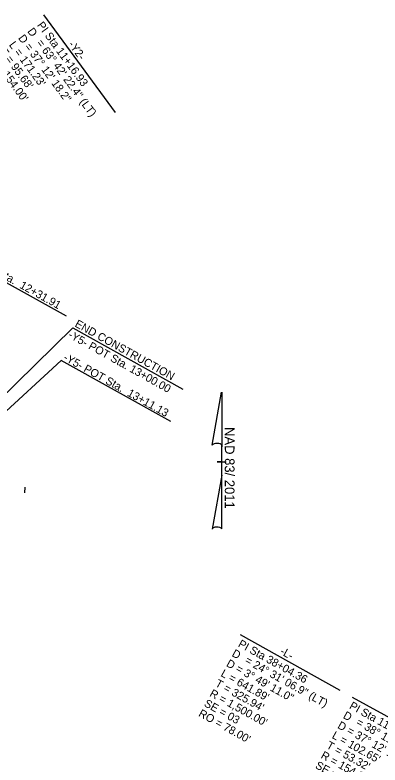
# Model space of a CAD drawing. Extents: x 1762196 to 1766326, y 709922 to 713142.
# Drawn here: x 1764411 to 1764730, y 711303 to 711959 of the extents above; entities that cross this region are included whole.
import ezdxf

# ---------------------------------------------------------------- set-up
doc = ezdxf.new("R2010")
doc.units = 0
for name, color, linetype in [('Pattern 1', 7, 'Continuous'), ('Pattern 2', 7, 'Continuous'), ('Prop Conc 2ft 6in Curb and Gutter', 7, 'Continuous'), ('Prop Dimension', 7, 'Continuous'), ('Prop EOT', 7, 'Continuous'), ('Prop Horizontal Alignment', 7, 'Continuous'), ('Prop Horizontal Alignment Curve and Spiral Data', 7, 'Continuous'), ('Prop Horizontal Alignment Station Label', 7, 'Continuous'), ('Prop Horizontal Alignment Tick Small', 7, 'Continuous'), ('Prop North Arrow NAD83 for Plan Sheets CELL', 7, 'Continuous')]:
    doc.layers.add(name, color=color, linetype=linetype)

msp = doc.modelspace()

# ---------------------------------------------------------------- linework, layer by layer
at = {"layer": 'Pattern 1'}
for radius in [1473.5, 1468.5]:
    msp.add_arc((1765296.46, 712280.56), radius, 220.01407, 240.8436, dxfattribs=at)
at = {"layer": 'Pattern 2'}
for radius in [1473.5, 1468.5]:
    msp.add_arc((1765296.46, 712280.56), radius, 220.01407, 240.8436, dxfattribs=at)
at = {"layer": 'Prop Conc 2ft 6in Curb and Gutter'}
msp.add_arc((1765296.46, 712280.56), 1478, 220.01407, 240.8436, dxfattribs=at)
at = {"layer": 'Prop Dimension'}
msp.add_arc((1765296.46, 712280.56), 1392.37, 222.11492, 230.90027, dxfattribs=at)
at = {"layer": 'Prop EOT'}
msp.add_arc((1765296.46, 712280.56), 1480, 220.01407, 240.8436, dxfattribs=at)
at = {"layer": 'Prop Horizontal Alignment'}
msp.add_arc((1765296.46, 712280.56), 1500, 216.32502, 240.8436, dxfattribs=at)
at = {"layer": 'Prop Horizontal Alignment Curve and Spiral Data'}
for p, q in [((1764435.5, 711959.06), (1764498.19, 711873.75)), ((1764607.52, 711417.28), (1764694.96, 711368.59)), ((1764705.67, 711362.62), (1764793.89, 711313.5))]:
    msp.add_line(p, q, dxfattribs=at)
at = {"layer": 'Prop Horizontal Alignment Station Label'}
for p, q in [((1764455.78, 711695.57), (1764364.45, 711746.43)), ((1764461.21, 711685.37), (1764319.42, 711546.5)), ((1764461.21, 711685.37), (1764557.4, 711631.8)), ((1764330.54, 711546.13), (1764451.2, 711656.86)), ((1764546.93, 711603.56), (1764451.2, 711656.86))]:
    msp.add_line(p, q, dxfattribs=at)
at = {"layer": 'Prop Horizontal Alignment Tick Small'}
msp.add_line((1764419.27, 711541.25), (1764419.57, 711546.25), dxfattribs=at)
at = {"layer": 'Prop North Arrow NAD83 for Plan Sheets CELL'}
for p, q in [((1764583.24, 711582.99), (1764591.44, 711629.34)), ((1764591.49, 711629.34), (1764591.49, 711581.54)), ((1764591.49, 711556.74), (1764591.49, 711582.94)), ((1764591.49, 711581.54), (1764591.49, 711582.89)), ((1764587.49, 711568.34), (1764587.44, 711568.34)), ((1764591.04, 711568.34), (1764587.49, 711568.34)), ((1764587.54, 711568.34), (1764595.54, 711568.34)), ((1764591.49, 711556.74), (1764583.14, 711509.49)), ((1764591.54, 711509.69), (1764591.49, 711556.74))]:
    msp.add_line(p, q, dxfattribs=at)
for centre, start_param, end_param in [((1764587.38, 711582.5), 0.216388, 2.908219), ((1764587.38, 711509.33), 0.201328, 3.141593)]:
    msp.add_ellipse(centre, major_axis=(4.23, -0.03), ratio=0.461098, start_param=start_param, end_param=end_param, dxfattribs=at)

# ---------------------------------------------------------------- texts
at = {"layer": 'Prop Horizontal Alignment Curve and Spiral Data'}
for s, rotation, p in [('PI Sta 11+16.93', 306.31306, (1764429.67, 711950.1)), ('D', 306.31306, (1764421.21, 711944.72)), ('D = 37%%d 12\' 18.2"', 306.31306, (1764413.15, 711938.8)), ("L = 171.23'", 306.31306, (1764405.09, 711932.88)), ('= 63%%d 42\' 22.4" (LT)', 306.31306, (1764429.06, 711934.54)), ('-Y2-', 306.31306, (1764456.9, 711933.27)), ("T = 95.68'", 306.31306, (1764397.04, 711926.96)), ("R = 154.00'", 306.31306, (1764388.98, 711921.03)), ('PI Sta 38+04.36', 330.88754, (1764605.24, 711407.11)), ('D', 330.88754, (1764599.78, 711398.7)), ('-L-', 330.88754, (1764641.88, 711400.65)), ('D = 3%%d 49\' 11.0"', 330.88754, (1764594.92, 711389.96)), ('= 24%%d 31\' 06.9" (LT)', 330.88754, (1764611.15, 711392.71)), ("L = 641.89'", 330.88754, (1764590.05, 711381.23)), ("T = 325.94'", 330.88754, (1764585.19, 711372.49)), ("R = 1,500.00'", 330.88754, (1764580.32, 711363.75)), ('SE = 03', 330.88754, (1764575.46, 711355.02)), ('PI Sta 11+82.58', 330.88754, (1764702.5, 711352.94)), ("RO = 78.00'", 330.88754, (1764570.59, 711346.28)), ('D', 330.88754, (1764697.05, 711344.53)), ('D = 37%%d 12\' 18.2"', 330.88754, (1764692.19, 711335.8)), ('= 38%%d 11\' 33.2" (RT)', 330.88754, (1764708.42, 711338.54)), ("L = 102.65'", 330.88754, (1764687.32, 711327.06)), ("T = 53.32'", 330.88754, (1764682.45, 711318.32)), ("R = 154.00'", 330.88754, (1764677.59, 711309.59)), ('SE = 02', 330.88754, (1764672.72, 711300.85))]:
    msp.add_text(s, height=7, rotation=rotation, dxfattribs=at).set_placement(p)
at = {"layer": 'Prop Horizontal Alignment Station Label'}
for s, p in [('-Y5- PT Sta.  12+31.91', (1764364.67, 711748.32)), ('END CONSTRUCTION', (1764462.41, 711686.91)), ('-Y5- POT Sta. 13+00.00', (1764456.58, 711677.41)), ('-Y5- POT Sta.  13+11.13', (1764452.37, 711657.57))]:
    msp.add_text(s, height=7, rotation=330.88754, dxfattribs=at).set_placement(p)
at = {"layer": 'Prop North Arrow NAD83 for Plan Sheets CELL'}
msp.add_text('NAD 83/ 2011', height=8.5, rotation=270, dxfattribs=at).set_placement((1764594.2, 711598.69))

doc.saveas('drawing.dxf')
